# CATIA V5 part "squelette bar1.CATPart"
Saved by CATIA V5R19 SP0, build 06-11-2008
Part number: squelette bar1
Publications: "Plan.1", "Longueur du bar", "demi_largeur du bar", "Droite.1", "Droite.2", "Droite.3", "Point.1", "Point.2"
Bounding box of the stored display mesh (mm): x 0 to 160, y 0 to 40, z 0 to 0
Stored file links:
  I:\yyang\yyang\squelette bar1.CATPart
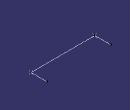
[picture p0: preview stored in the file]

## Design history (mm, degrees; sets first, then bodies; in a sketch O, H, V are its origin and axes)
Parameters
  `Longueur du bar` = 160 mm
  `demi_largeur du bar` = 10 mm
Body1 (main body)
  Plane1: type Offset, Offset 0, RefPlane zx-plane
  Point1: (0, 0, 0)
  Point2: (160 {= `Longueur du bar`}, 0, 0)
  Line1: type PtPt, SecondPoint Point2, FirstPoint Point1
  Line2: type PtDir, Direction (0, 1, 0), Start 0, End 40, RefPoint Point1
  Line3: type PtDir, Direction (0, 1, 0), Start 0, End 40, RefPoint Point2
